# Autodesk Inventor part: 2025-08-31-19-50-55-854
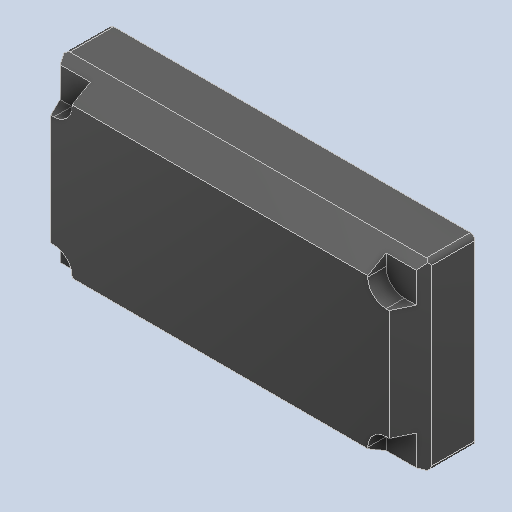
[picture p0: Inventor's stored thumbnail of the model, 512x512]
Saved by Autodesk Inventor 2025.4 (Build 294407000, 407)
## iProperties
Created: 2026-09
Part Number: 2025-08-31-19-50-55-854
Material: Generic
Document SubType Name: Modeling
Designer: AdminForWorker
Density: 1 g/cm^3
Appearance: Default
Title: com_but
Author: AdminForWorker
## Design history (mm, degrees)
feature "Body1"
body "Solid1"
